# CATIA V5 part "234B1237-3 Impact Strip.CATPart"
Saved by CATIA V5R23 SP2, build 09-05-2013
Part number: 234B1237-3 Impact Strip
Bounding box of the stored display mesh (mm): x 31562.891 to 31575.795, y -11305.193 to -11279.317, z 5320.39 to 5424.898
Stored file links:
  C:\Users\rem1927\Desktop\Current Explicit Composite Demo\234B1237-3 Impact Strip.CATPart
  C:\Users\rem1927\Desktop\Current Explicit Composite Demo\234B5678-1 Composite Product.CATProduct
  C:\Users\rem1927\Desktop\Current Explicit Composite Demo\234B5678_2_Rev_.CATPart
  C:\Program Files\Dassault Systemes\B23SP2PRALL\win_b64\startup\materials\brushed_metal1.jpg
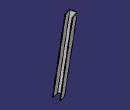
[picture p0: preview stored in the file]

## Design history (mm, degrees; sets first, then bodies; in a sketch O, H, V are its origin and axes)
WSupportSet1
Set1
  Intersect1: ToIntersect1 DatumCurve1, ToIntersect2 DatumCurve2
  Plane1: type Normal, Curve DatumCurve1, RefPoint Intersect1
  Project1: ToProject DatumCurve2, Support Plane1
  Point1: type OnPlane, OnSupport {wsupport Support Plane1, RefPoint Intersect1, GridIn {cartgrid StepH1 25.4, StepH2 10, StepV1 25.4, StepV2 10, Direction Project1}}, Support Plane1, RefPoint Intersect1, H 8.89, V 0, Direction Project1
  Point2: type OnPlane, OnSupport {wsupport Support Plane1, RefPoint Intersect1, GridIn {cartgrid StepH1 25.4, StepH2 10, StepV1 25.4, StepV2 10, Direction Project1}}, Support Plane1, RefPoint Intersect1, H 8.89, V 7.0358, Direction Project1
  Point3: type OnPlane, OnSupport {wsupport Support Plane1, RefPoint Intersect1, GridIn {cartgrid StepH1 25.4, StepH2 10, StepV1 25.4, StepV2 10, Direction Project1}}, Support Plane1, RefPoint Intersect1, H 0, V 7.0358, Direction Project1
  Line1: type PtPt, OnSupport {wsupport Support Plane1, RefPoint Intersect1, GridIn {cartgrid StepH1 25.4, StepH2 10, StepV1 25.4, StepV2 10, Direction Project1}}, FirstPoint Point2, SecondPoint Point3, Support Plane1
  Line2: type PtPt, OnSupport {wsupport Support Plane1, RefPoint Intersect1, GridIn {cartgrid StepH1 25.4, StepH2 10, StepV1 25.4, StepV2 10, Direction Project1}}, FirstPoint Point1, SecondPoint Intersect1, Support Plane1
  Line3: type PtPt, OnSupport {wsupport Support Plane1, RefPoint Intersect1, GridIn {cartgrid StepH1 25.4, StepH2 10, StepV1 25.4, StepV2 10, Direction Project1}}, FirstPoint Point3, SecondPoint Intersect1, Support Plane1
  CurvePar1: OnSupport {wsupport Support Plane1, RefPoint Intersect1, GridIn {cartgrid StepH1 25.4, StepH2 10, StepV1 25.4, StepV2 10, Direction Project1}}, Offset Line1, Support Plane1, Offset2 0, Offset1 0.762
  CurvePar2: OnSupport {wsupport Support Plane1, RefPoint Intersect1, GridIn {cartgrid StepH1 25.4, StepH2 10, StepV1 25.4, StepV2 10, Direction Project1}}, Offset Line2, Support Plane1, Offset2 0, Offset1 0.762
  Line4: type PtPt, OnSupport {wsupport Support Plane1, RefPoint Intersect1, GridIn {cartgrid StepH1 25.4, StepH2 10, StepV1 25.4, StepV2 10, Direction Project1}}, FirstPoint Point3, SecondPoint Intersect1, Support Plane1
  CurvePar3: OnSupport {wsupport Support Plane1, RefPoint Intersect1, GridIn {cartgrid StepH1 25.4, StepH2 10, StepV1 25.4, StepV2 10, Direction Project1}}, Offset Line4, Support Plane1, Offset2 0, Offset1 0.762
  Corner1: Element1 CurvePar1, OnSupport {wsupport Support Plane1, RefPoint Intersect1, GridIn {cartgrid StepH1 25.4, StepH2 10, StepV1 25.4, StepV2 10, Direction Project1}}, Element2 CurvePar3, Support Plane1, Radius 0.889
  Corner2: Element1 Corner1, OnSupport {wsupport Support Plane1, RefPoint Intersect1, GridIn {cartgrid StepH1 25.4, StepH2 10, StepV1 25.4, StepV2 10, Direction Project1}}, Element2 CurvePar2, Support Plane1, Radius 0.889
  Line5: type PtPt, OnSupport {wsupport Support Plane1, RefPoint Intersect1, GridIn {cartgrid StepH1 25.4, StepH2 10, StepV1 25.4, StepV2 10, Direction Project1}}, FirstPoint vertex of CurvePar2, SecondPoint Point1, Support Plane1
  Line6: type PtPt, OnSupport {wsupport Support Plane1, RefPoint Intersect1, GridIn {cartgrid StepH1 25.4, StepH2 10, StepV1 25.4, StepV2 10, Direction Project1}}, FirstPoint vertex of CurvePar1, SecondPoint Point2, Support Plane1
  Join1: Elements (Line2; Line5; Corner2; Line6; Line1; Line4), OnSupport {wsupport Support Plane1, RefPoint Intersect1, GridIn {cartgrid StepH1 25.4, StepH2 10, StepV1 25.4, StepV2 10, Direction Project1}}
Set2
  DatumCurve1: linked copy from another document
  DatumCurve2: linked copy from another document
Body1 "Impact Strip" (main body)
  Pad1: profile Join1, length 40.64, opposite side length 63.5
